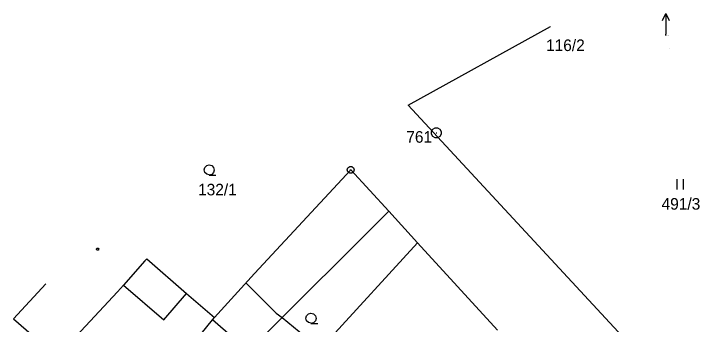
# Model space of a CAD drawing. Extents: x -755359 to -754474, y -1162585 to -1161655.
# Drawn here: x -754971.6 to -754872, y -1161700.1 to -1161654.5 of the extents above; entities that cross this region are included whole.
import ezdxf

# ---------------------------------------------------------------- set-up
doc = ezdxf.new("R2010")
doc.units = 0
for name, color, linetype in [('Vrstva 1', 7, 'Continuous'), ('Vrstva 11', 7, 'Continuous'), ('Vrstva 12', 7, 'Continuous'), ('Vrstva 2', 7, 'Continuous'), ('Vrstva 3', 7, 'Continuous'), ('Vrstva 4', 7, 'Continuous'), ('Vrstva 5', 7, 'Continuous'), ('Vrstva 7', 7, 'Continuous'), ('Vrstva 8', 7, 'Continuous')]:
    doc.layers.add(name, color=color, linetype=linetype)

msp = doc.modelspace()

# ---------------------------------------------------------------- linework, layer by layer
at = {"layer": 'Vrstva 1'}
for p, q in [((-754913.71, -1161667.99), (-754892.83, -1161656.43)), ((-754892.83, -1161656.43), (-754892.83, -1161656.43)), ((-754892.83, -1161656.43), (-754892.83, -1161656.43)), ((-754892.83, -1161656.43), (-754892.83, -1161656.43)), ((-754875.36, -1161659.59), (-754875.36, -1161659.59)), ((-754875.36, -1161659.59), (-754875.36, -1161659.59)), ((-754913.71, -1161667.99), (-754913.71, -1161667.99)), ((-754871.95, -1161713.02), (-754913.71, -1161667.99)), ((-754922.12, -1161677.47), (-754936.26, -1161692.66)), ((-754922.12, -1161677.47), (-754922.12, -1161677.47)), ((-754922.12, -1161677.47), (-754916.55, -1161683.55)), ((-754937.15, -1161704.08), (-754916.55, -1161683.55)), ((-754916.55, -1161683.55), (-754912.31, -1161688.18)), ((-754948.77, -1161727.83), (-754912.31, -1161688.18)), ((-754912.31, -1161688.18), (-754900.61, -1161700.97)), ((-754952.35, -1161690.83), (-754952.05, -1161690.53)), ((-754952.05, -1161690.53), (-754952.05, -1161690.53)), ((-754952.05, -1161690.53), (-754946.21, -1161695.6)), ((-754952.35, -1161690.83), (-754955.48, -1161694.38)), ((-754936.26, -1161692.66), (-754942.13, -1161699.15)), ((-754955.48, -1161694.38), (-754956.37, -1161695.39)), ((-754956.37, -1161695.39), (-754964.42, -1161704)), ((-754946.21, -1161695.6), (-754942.13, -1161699.15)), ((-754944.06, -1161701.54), (-754942.4, -1161699.49)), ((-754942.4, -1161699.49), (-754942.13, -1161699.15))]:
    msp.add_line(p, q, dxfattribs=at)
at = {"layer": 'Vrstva 11'}
for p, q in [((-754937.54, -1161694.07), (-754933.05, -1161698.48)), ((-754933.05, -1161698.48), (-754932.21, -1161699.15)), ((-754932.21, -1161699.15), (-754926.59, -1161703.71))]:
    msp.add_line(p, q, dxfattribs=at)
at = {"layer": 'Vrstva 12'}
for p, q in [((-754966.87, -1161694.19), (-754971.61, -1161699.33)), ((-754966.87, -1161694.19), (-754966.87, -1161694.19)), ((-754971.61, -1161699.33), (-754965.35, -1161704.72))]:
    msp.add_line(p, q, dxfattribs=at)
at = {"layer": 'Vrstva 3'}
for p, q in [((-754874.28, -1161678.85), (-754874.28, -1161680.35)), ((-754873.28, -1161680.35), (-754873.28, -1161678.85))]:
    msp.add_line(p, q, dxfattribs=at)
for points in [[(-754942.89, -1161678.22), (-754943.27, -1161678.12), (-754943.54, -1161677.85), (-754943.64, -1161677.48), (-754943.54, -1161677.11), (-754943.27, -1161676.84), (-754942.9, -1161676.74), (-754942.53, -1161676.84), (-754942.26, -1161677.11), (-754942.16, -1161677.49), (-754942.26, -1161677.87), (-754942.53, -1161678.14), (-754942.91, -1161678.24), (-754941.91, -1161678.24)], [(-754927.95, -1161699.99), (-754928.33, -1161699.89), (-754928.6, -1161699.62), (-754928.7, -1161699.25), (-754928.6, -1161698.88), (-754928.33, -1161698.61), (-754927.96, -1161698.51), (-754927.59, -1161698.61), (-754927.32, -1161698.88), (-754927.22, -1161699.26), (-754927.32, -1161699.64), (-754927.59, -1161699.91), (-754927.97, -1161700.01), (-754926.97, -1161700.01)]]:
    msp.add_lwpolyline(points, dxfattribs=at)
at = {"layer": 'Vrstva 4'}
for p, q in [((-754952.35, -1161690.83), (-754952.35, -1161690.83)), ((-754966.87, -1161694.19), (-754971.61, -1161699.33)), ((-754966.87, -1161694.19), (-754966.87, -1161694.19)), ((-754955.48, -1161694.38), (-754949.56, -1161699.46)), ((-754956.37, -1161695.39), (-754956.37, -1161695.39)), ((-754949.56, -1161699.46), (-754946.21, -1161695.6)), ((-754971.61, -1161699.33), (-754965.35, -1161704.72)), ((-754939.32, -1161702.19), (-754942.4, -1161699.49))]:
    msp.add_line(p, q, dxfattribs=at)
at = {"layer": 'Vrstva 5'}
msp.add_lwpolyline([(-754959.19, -1161688.94), (-754959.1, -1161689.09), (-754959.19, -1161689.24), (-754959.37, -1161689.24), (-754959.46, -1161689.09), (-754959.37, -1161688.94)], close=True, dxfattribs=at)
at = {"layer": 'Vrstva 7'}
for p in [(-754875.88, -1161654.53), (-754875.88, -1161657.75)]:
    msp.add_line(p, (-754875.88, -1161657.53), dxfattribs=at)
msp.add_lwpolyline([(-754876.38, -1161655.53), (-754875.88, -1161654.53), (-754875.38, -1161655.53)], dxfattribs=at)
at = {"layer": 'Vrstva 8'}
for p, q in [((-754909.61, -1161672.04), (-754909.51, -1161672.04)), ((-754922.24, -1161677.47), (-754922, -1161677.47))]:
    msp.add_line(p, q, dxfattribs=at)
for points in [[(-754909.37, -1161671.32), (-754909.03, -1161671.51), (-754908.84, -1161671.85), (-754908.84, -1161672.24), (-754909.03, -1161672.58), (-754909.37, -1161672.77), (-754909.76, -1161672.77), (-754910.1, -1161672.58), (-754910.29, -1161672.24), (-754910.29, -1161671.85), (-754910.1, -1161671.51), (-754909.76, -1161671.32)], [(-754921.97, -1161676.99), (-754921.72, -1161677.17), (-754921.62, -1161677.46), (-754921.72, -1161677.75), (-754921.97, -1161677.93), (-754922.28, -1161677.93), (-754922.53, -1161677.75), (-754922.63, -1161677.46), (-754922.53, -1161677.17), (-754922.28, -1161676.99)]]:
    msp.add_lwpolyline(points, close=True, dxfattribs=at)

# ---------------------------------------------------------------- texts
at = {"layer": 'Vrstva 2'}
for s, height, p in [('491/4', 0.1, (-754875.866, -1161657.75)), ('132/1', 1.7, (-754944.537, -1161681.21)), ('491/3', 1.7, (-754876.513, -1161683.31))]:
    msp.add_text(s, height=height, dxfattribs=at).set_placement(p)
at = {"layer": 'Vrstva 7'}
msp.add_text('116/2', height=1.7, dxfattribs=at).set_placement((-754893.469, -1161660.03))
at = {"layer": 'Vrstva 8'}
msp.add_text('761', height=1.7, dxfattribs=at).set_placement((-754913.973, -1161673.48))

doc.saveas('drawing.dxf')
